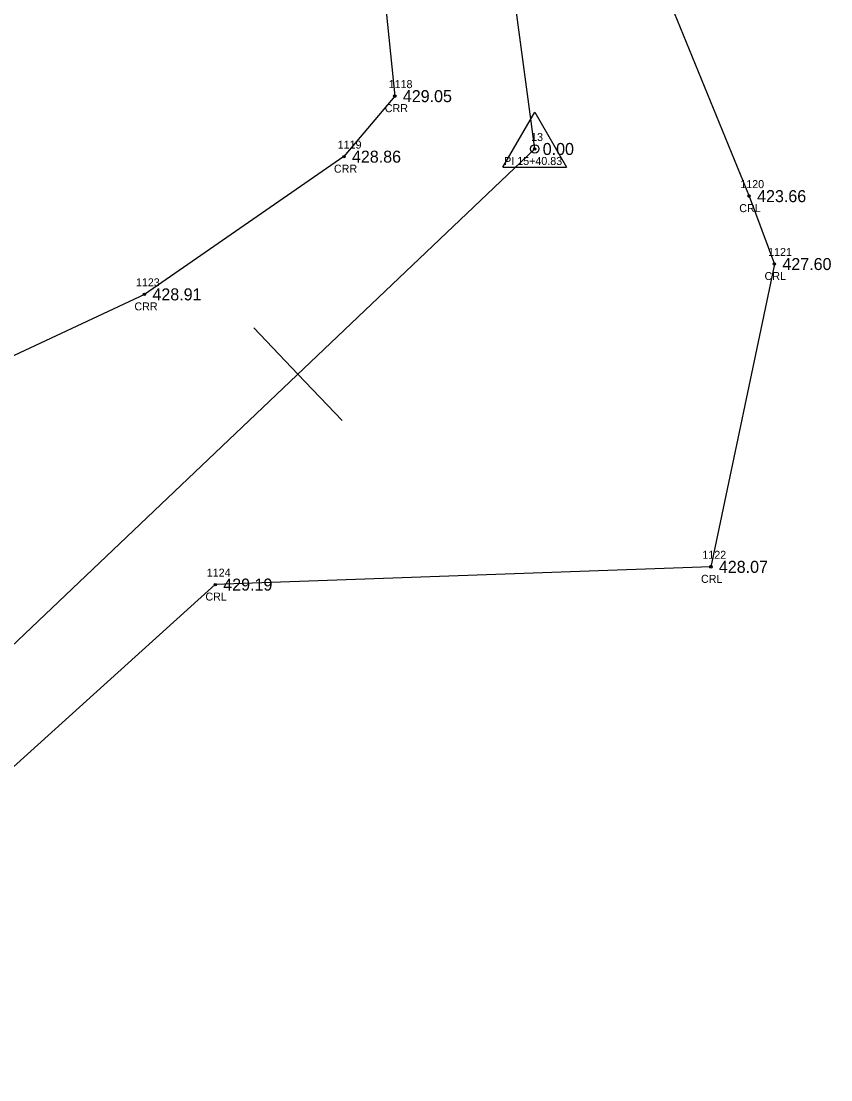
# Model space of a CAD drawing. Extents: x 1858454 to 1858924, y 1147053 to 1148170.
# Drawn here: x 1858800.8 to 1858902, y 1147671.2 to 1147803.4 of the extents above; entities that cross this region are included whole.
import ezdxf

# ---------------------------------------------------------------- set-up
doc = ezdxf.new("R2010")
doc.units = 0
for name, color, linetype in [('RD_EX_H2O', 7, 'Continuous'), ('RD_EX_H2O_txCode', 7, 'Continuous'), ('RD_EX_TX_H2O_ELEV', 7, 'Continuous'), ('RD_HC_Cl', 7, 'Continuous'), ('RD_HC_Data', 7, 'Continuous'), ('RD_HC_Data_Tic', 7, 'Continuous'), ('RD_HC_Survey_ELEV', 7, 'Continuous'), ('RD_HC_txCode', 7, 'Continuous'), ('RD_SMD_Locator', 7, 'Continuous')]:
    doc.layers.add(name, color=color, linetype=linetype)

msp = doc.modelspace()

# ---------------------------------------------------------------- linework, layer by layer
at = {"layer": 'RD_EX_H2O'}
for points in [[(1858879.83, 1148102.54), (1858871.42, 1148034.27), (1858866.93, 1147971.73), (1858863.21, 1147909.44), (1858860.9, 1147860.04), (1858873.82, 1147825.54), (1858891.79, 1147781.55), (1858894.95, 1147773.07), (1858887.01, 1147735.25), (1858825.08, 1147733.03), (1858791.14, 1147702.41), (1858765.02, 1147654.77), (1858740.99, 1147628.76), (1858706.35, 1147596.83), (1858671.87, 1147580.02), (1858637.61, 1147560.56), (1858613.46, 1147539.88), (1858609.2, 1147499), (1858608.26, 1147474.71), (1858583.43, 1147442.99), (1858542.68, 1147417.32), (1858497.34, 1147430.55)], [(1858842, 1147848.22), (1858847.52, 1147794.04), (1858841.16, 1147786.48), (1858816.23, 1147769.28), (1858759.58, 1147742.8), (1858751.47, 1147732.35), (1858731.2, 1147689.66), (1858724.77, 1147677.64), (1858718.76, 1147662.14), (1858713.87, 1147646.5), (1858696.23, 1147629.99), (1858681.73, 1147631.9), (1858663.61, 1147613.98), (1858627.73, 1147602.37), (1858587.46, 1147561.81), (1858570.79, 1147529.07), (1858577.35, 1147512.16), (1858564.18, 1147528.65), (1858536.5, 1147564.8), (1858503.8, 1147609.24)]]:
    msp.add_lwpolyline(points, dxfattribs=at)
at = {"layer": 'RD_HC_Cl'}
for p, q in [((1858865, 1147787.44), (1858842.19, 1147958.88)), ((1858683.96, 1147615.39), (1858865, 1147787.44))]:
    msp.add_line(p, q, dxfattribs=at)
at = {"layer": 'RD_HC_Data'}
for p, q in [((1858861.03, 1147785.15), (1858865, 1147792.03)), ((1858865, 1147792.03), (1858868.97, 1147785.15)), ((1858861.03, 1147785.15), (1858868.97, 1147785.15))]:
    msp.add_line(p, q, dxfattribs=at)
msp.add_circle((1858865, 1147787.44), 0.529, dxfattribs=at)
at = {"layer": 'RD_HC_Data_Tic'}
for q in [(1858829.9, 1147765.12), (1858840.92, 1147753.52)]:
    msp.add_line((1858835.41, 1147759.32), q, dxfattribs=at)
at = {"layer": 'RD_SMD_Locator'}
for centre in [(1858847.52, 1147794.04), (1858865, 1147787.44), (1858841.16, 1147786.48), (1858891.79, 1147781.55), (1858894.95, 1147773.07), (1858816.23, 1147769.28), (1858887.01, 1147735.25), (1858825.08, 1147733.03)]:
    msp.add_circle(centre, 0.15, dxfattribs=at)

# ---------------------------------------------------------------- texts
at = {"layer": 'RD_EX_H2O_txCode'}
for s, p in [('1118', (1858846.75, 1147795.04)), ('CRR', (1858846.27, 1147792.04)), ('1119', (1858840.38, 1147787.48)), ('CRR', (1858839.91, 1147784.48)), ('1120', (1858890.69, 1147782.55)), ('CRL', (1858890.56, 1147779.55)), ('1121', (1858894.17, 1147774.07)), ('CRL', (1858893.72, 1147771.07)), ('1123', (1858815.17, 1147770.28)), ('CRR', (1858814.98, 1147767.28)), ('1122', (1858885.95, 1147736.25)), ('1124', (1858824.02, 1147734.03)), ('CRL', (1858885.78, 1147733.25)), ('CRL', (1858823.85, 1147731.03))]:
    msp.add_text(s, height=1, dxfattribs=at).set_placement(p)
at = {"layer": 'RD_EX_TX_H2O_ELEV'}
for s, p in [('429.05', (1858848.52, 1147793.29)), ('428.86', (1858842.16, 1147785.73)), ('423.66', (1858892.79, 1147780.8)), ('427.60', (1858895.95, 1147772.32)), ('428.91', (1858817.23, 1147768.53)), ('428.07', (1858888.01, 1147734.5)), ('429.19', (1858826.08, 1147732.28))]:
    msp.add_text(s, height=1.5, dxfattribs=at).set_placement(p)
at = {"layer": 'RD_HC_Survey_ELEV'}
msp.add_text('0.00', height=1.5, dxfattribs=at).set_placement((1858866, 1147786.69))
at = {"layer": 'RD_HC_txCode'}
for s, p in [('13', (1858864.55, 1147788.44)), ('PI 15+40.83', (1858861.18, 1147785.44))]:
    msp.add_text(s, height=1, dxfattribs=at).set_placement(p)

doc.saveas('drawing.dxf')
